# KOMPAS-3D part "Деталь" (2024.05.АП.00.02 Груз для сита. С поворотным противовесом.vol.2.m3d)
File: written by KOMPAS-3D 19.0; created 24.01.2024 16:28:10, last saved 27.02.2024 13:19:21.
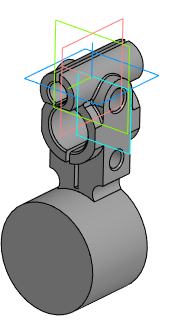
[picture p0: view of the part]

Document properties: Автор: mail.maksim@mail.ru; Полное имя файла: O:\Самозанятый. Полынский М.И\Агропак\04 Проекты 2024 года\2024.05.АП.00.00 Грузы для сита. Хартманн 1 и 2\2024.05.АП.00.00 Чертежи\2024.05.АП 3D модели\2024.05.АП.00.02 Груз для сита. С поворотным противовесом.vol.2.m3d

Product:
- Part/product: Деталь
    Масса: 1.43835

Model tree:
1. Эскиз:1
2. Элемент выдавливания:1
     Расстояние 1 = 37
3. Эскиз:2  (with: Элемент выдавливания:1)
4. Элемент выдавливания:2
     Расстояние 1 = 10
5. Эскиз:3  (with: Элемент выдавливания:1)
6. Элемент выдавливания:3
     Расстояние 1 = 10
7. Эскиз:4  (with: Элемент выдавливания:3, Элемент выдавливания:1)
8. Эскиз:6  (with: Элемент выдавливания:1)
9. Элемент выдавливания:6
     Расстояние 2 = 37
10. Эскиз:7  (with: Элемент выдавливания:6)
11. Элемент выдавливания:7
     Расстояние 2 = 36
12. Эскиз:8  (with: Элемент выдавливания:6, Элемент выдавливания:7)
13. Элемент выдавливания:8
     Расстояние 2 = 36
14. Элемент выдавливания:9
     Расстояние 2 = 63
15. Скругление:1  (with: Элемент выдавливания:1)
     Радиус = 2
16. Скругление:2  (with: Элемент выдавливания:1)
     Радиус = 2
17. Скругление:3  (with: Элемент выдавливания:7)
     Радиус = 1
18. Скругление:4  (with: Элемент выдавливания:7)
     Радиус = 1
19. Фаска:1  (with: Элемент выдавливания:7, Элемент выдавливания:9)
     Угол = 45; Длина 1 = 1; Длина 2 = 1
20. Эскиз:9  (with: Элемент выдавливания:3)
21. Элемент выдавливания:10
     Расстояние 2 = 57
22. Смещенная плоскость:1  (with: Элемент выдавливания:1)
     Расстояние = 7.5
23. Эскиз:10
24. Элемент выдавливания:17
     Расстояние 2 = 45
25. Эскиз:11  (with: Элемент выдавливания:17, Элемент выдавливания:6, Элемент выдавливания:7, Элемент выдавливания:1)
26. Элемент выдавливания:18
     Расстояние 2 = 22
27. Эскиз:12  (with: Элемент выдавливания:6, Фаска:1)
28. Элемент выдавливания:19
     Расстояние 2 = 36
29. Эскиз:13  (with: Элемент выдавливания:1, Элемент выдавливания:7)
30. Элемент выдавливания:20
     Расстояние 2 = 37
31. Фаска:2  (with: Элемент выдавливания:19)
     Угол = 45; Длина 1 = 1; Длина 2 = 1
32. Фаска:3  (with: Элемент выдавливания:19)
     Угол = 45; Длина 1 = 1; Длина 2 = 1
